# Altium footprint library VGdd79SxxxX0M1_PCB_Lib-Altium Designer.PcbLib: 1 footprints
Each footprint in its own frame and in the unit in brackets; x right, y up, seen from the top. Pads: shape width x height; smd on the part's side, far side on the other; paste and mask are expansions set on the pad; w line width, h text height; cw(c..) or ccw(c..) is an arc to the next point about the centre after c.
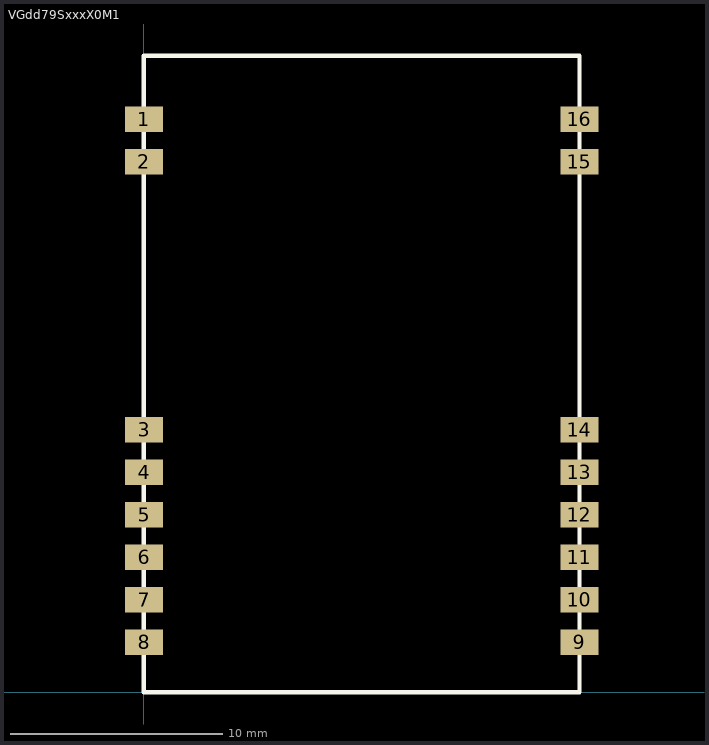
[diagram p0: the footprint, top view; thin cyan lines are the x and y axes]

## VGdd79SxxxX0M1 [mm]
pads (17):
  round 1.2 on Top Overlay: 1(-1.016,28.702)
  rect 1.8x1.2 smd: 1(0.006,26.96) 2(0.006,24.96) 3(0.01,12.35) 4(0.01,10.35) 5(0.01,8.35) 6(0.01,6.35) 7(0.01,4.35) 8(0.01,2.35) 9(20.5,2.35) 10(20.5,4.35) 11(20.5,6.35) 12(20.5,8.35) 13(20.5,10.35) 14(20.5,12.35) 15(20.5,24.96) 16(20.5,26.96)
Top Overlay:
  lines w0.2: 0,0 0,29.95 20.5,29.95 ; 0,0 0,0 ; 0,0 20.5,0 20.5,29.95 ; 20.5,29.95 20.5,29.95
